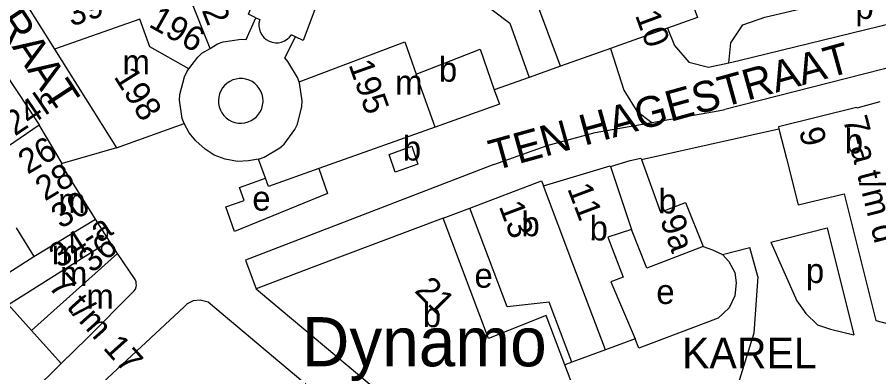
# Model space of a CAD drawing. Extents: x 160673 to 161924, y 382258 to 384145.
# Drawn here: x 161438.3 to 161578.5, y 383169.3 to 383227.2 of the extents above; entities that cross this region are included whole.
import ezdxf

# ---------------------------------------------------------------- set-up
doc = ezdxf.new("R2010")
doc.units = 0
for name, color, linetype in [('BLT_Basislijn', 7, 'Continuous'), ('BLT_Bebouwing', 7, 'Continuous'), ('BLT_Bebouwing_beschrifting', 7, 'Continuous'), ('BLT_Centroide', 7, 'Continuous'), ('BLT_Huisnummer', 7, 'Continuous'), ('BLT_Huisnummer_reeks', 7, 'Continuous'), ('BLT_Onderverdeling_panden', 7, 'Continuous'), ('BLT_Straatnaam', 7, 'Continuous'), ('BLT_Vlakafsluiter', 7, 'Continuous')]:
    doc.layers.add(name, color=color, linetype=linetype)

msp = doc.modelspace()

# ---------------------------------------------------------------- linework, layer by layer
at = {"layer": 'BLT_Basislijn'}
for p, q in [((161608.47, 383226.14), (161553.47, 383212.15)), ((161541.58, 383210.02), (161552.39, 383211.91)), ((161552.39, 383211.91), (161553.47, 383212.15)), ((161539.92, 383203.99), (161562.24, 383209)), ((161507.62, 383194.44), (161512, 383196.09)), ((161560.96, 383190.54), (161570.14, 383192.89)), ((161553.08, 383188.52), (161557.52, 383189.66)), ((161528.58, 383171), (161527.45, 383170.59))]:
    msp.add_line(p, q, dxfattribs=at)
for points in [[(161554.12, 383219.74), (161554.47, 383223.02), (161556.42, 383225.91), (161559.99, 383227.18), (161594.98, 383235.4), (161599.22, 383233.8)], [(161554.12, 383219.74), (161555.77, 383220.1), (161601.53, 383231.34)], [(161544.14, 383225.4), (161545.29, 383222.57), (161547.63, 383219.86), (161550.8, 383219.01), (161554.12, 383219.74)], [(161534.87, 383222.09), (161537.05, 383215.31), (161539.13, 383211.89), (161541.58, 383210.02)], [(161478.33, 383213.55), (161478.29, 383214.09), (161478.17, 383214.61), (161477.98, 383215.11), (161477.71, 383215.58), (161477.38, 383216), (161476.98, 383216.37), (161476.54, 383216.68), (161476.06, 383216.92), (161475.54, 383217.08), (161475.01, 383217.17), (161474.47, 383217.17), (161473.94, 383217.1), (161473.42, 383216.95), (161472.93, 383216.72), (161472.48, 383216.43), (161472.08, 383216.07), (161471.74, 383215.65), (161471.46, 383215.19), (161471.25, 383214.69), (161471.12, 383214.17), (161471.07, 383213.64), (161471.1, 383213.1), (161471.2, 383212.57), (161471.39, 383212.06), (161471.64, 383211.59), (161471.97, 383211.16), (161472.35, 383210.78), (161472.79, 383210.46), (161473.26, 383210.21), (161473.77, 383210.04), (161474.3, 383209.94), (161474.84, 383209.92), (161475.37, 383209.98), (161475.89, 383210.12), (161476.39, 383210.34), (161476.85, 383210.62), (161477.26, 383210.97), (161477.61, 383211.38), (161477.9, 383211.83), (161478.12, 383212.32), (161478.26, 383212.84), (161478.33, 383213.38), (161478.33, 383213.55)], [(161477.62, 383204.04), (161475.99, 383203.79), (161474.17, 383203.7), (161472.15, 383204.07), (161470.39, 383204.71), (161468.89, 383205.67), (161467.38, 383207.04), (161466.33, 383208.33), (161465.48, 383209.86)], [(161515.87, 383203.21), (161524.58, 383206.29), (161532.36, 383208.39), (161541.58, 383210.02)], [(161515.87, 383203.21), (161475.47, 383187.61), (161477.23, 383182.96)], [(161487.41, 383202.53), (161488.84, 383198.48)], [(161473.69, 383192.29), (161472.29, 383196.3), (161475.25, 383197.34), (161474.51, 383199.44), (161478.75, 383200.96)], [(161488.84, 383198.48), (161473.69, 383192.29)], [(161549.92, 383189.82), (161551.47, 383189.28), (161553.08, 383188.52)], [(161558.84, 383184.96), (161557.52, 383189.66)], [(161560.96, 383190.54), (161565.18, 383181.02), (161566.66, 383178.94), (161568.56, 383177.12), (161570.68, 383176.37), (161574.47, 383175.48)], [(161553.08, 383188.52), (161554.1, 383187.38), (161555.08, 383185.59), (161555.32, 383183.91), (161555.12, 383181.79), (161554.17, 383179.89), (161552.37, 383178.17), (161539.45, 383173.28), (161538.87, 383174.83)], [(161558.84, 383184.96), (161558.18, 383175.74), (161555.16, 383165.91), (161549.27, 383153.85), (161548.57, 383152.74), (161546.98, 383149.44), (161541.17, 383143.92)], [(161485.03, 383165.97), (161485.83, 383166.97), (161470.47, 383179.86), (161469.39, 383180.76), (161468.12, 383181.13), (161466.99, 383181.02), (161466.01, 383180.53), (161465.51, 383180.03), (161432.72, 383149.6), (161432.07, 383148.78), (161431.81, 383147.93), (161431.86, 383146.84), (161432.5, 383145.53), (161446.92, 383128.91), (161448.52, 383130.38)]]:
    msp.add_lwpolyline(points, dxfattribs=at)
at = {"layer": 'BLT_Bebouwing'}
for p, q in [((161478.75, 383200.96), (161477.62, 383204.04)), ((161479.24, 383199.61), (161478.75, 383200.96)), ((161453.36, 383190.71), (161451.1, 383194.27)), ((161454.64, 383188.7), (161453.36, 383190.71)), ((161457.54, 383184.45), (161454.64, 383188.7)), ((161486.19, 383186.35), (161477.23, 383182.96)), ((161477.62, 383182.63), (161516.83, 383149.75)), ((161534.05, 383173.01), (161528.58, 383171)), ((161529.67, 383164.74), (161527.45, 383170.59))]:
    msp.add_line(p, q, dxfattribs=at)
for points in [[(161441.57, 383231.12), (161439.44, 383229.84), (161444.39, 383221.97)], [(161551.93, 383231.15), (161548.05, 383229.78), (161549.02, 383227.14), (161544.14, 383225.4)], [(161469.72, 383222.09), (161470.94, 383222.81), (161471.82, 383223.14), (161474.76, 383223.57), (161475.58, 383223.52), (161477.14, 383227.08)], [(161477.14, 383227.08), (161477.79, 383226.77)], [(161477.79, 383226.77), (161477.67, 383226.22), (161477.65, 383225.73), (161477.73, 383225.2), (161477.85, 383224.81), (161478.14, 383224.27), (161478.46, 383223.87), (161478.84, 383223.54), (161479.32, 383223.26), (161479.83, 383223.08), (161480.35, 383222.99), (161480.87, 383223.01), (161481.36, 383223.11), (161481.85, 383223.3), (161482.28, 383223.57), (161482.66, 383223.91), (161482.96, 383224.3)], [(161544.14, 383225.4), (161534.87, 383222.09)], [(161484.23, 383216.62), (161483.95, 383217.36), (161482.39, 383219.93), (161481.86, 383220.55), (161483.64, 383223.98)], [(161483.64, 383223.98), (161482.96, 383224.3)], [(161444.39, 383221.97), (161454.47, 383205.92)], [(161466.26, 383218.74), (161467.71, 383220.67), (161468.39, 383221.31), (161469.72, 383222.09)], [(161534.87, 383222.09), (161526.73, 383219.19)], [(161434.47, 383220.8), (161441.92, 383209.63)], [(161526.73, 383219.19), (161521.62, 383217.37)], [(161454.47, 383205.92), (161465.48, 383209.86), (161465.18, 383210.7), (161464.76, 383213.64), (161464.8, 383214.58), (161465.54, 383217.46), (161465.92, 383218.3), (161466.26, 383218.74)], [(161521.62, 383217.37), (161515.96, 383215.34)], [(161477.62, 383204.04), (161478.5, 383204.37), (161481.05, 383205.89), (161481.75, 383206.52), (161483.52, 383208.9), (161483.92, 383209.74), (161484.67, 383212.64), (161484.7, 383213.58), (161484.27, 383216.51), (161484.23, 383216.62)], [(161515.96, 383215.34), (161516.79, 383213.01)], [(161578.69, 383213.41), (161574.95, 383212.36), (161574.91, 383212.48), (161562.22, 383209.32), (161562.24, 383209)], [(161516.79, 383213.01), (161506.32, 383209.27)], [(161445.63, 383203.34), (161441.92, 383209.63)], [(161506.32, 383209.27), (161487.41, 383202.53)], [(161562.24, 383209), (161563.49, 383204.16), (161565.39, 383196.62), (161572.89, 383198.41), (161574.02, 383193.88)], [(161534.89, 383202.87), (161538.04, 383203.83), (161539.81, 383204.22), (161539.92, 383203.99)], [(161539.92, 383203.99), (161542.99, 383195.43), (161547.06, 383196.99), (161549.92, 383189.82)], [(161451.1, 383194.27), (161445.47, 383203.23), (161445.63, 383203.34)], [(161487.41, 383202.53), (161479.24, 383199.61)], [(161523.98, 383199.7), (161534.82, 383202.97), (161534.89, 383202.87)], [(161512, 383196.09), (161523.66, 383200.51), (161523.98, 383199.7)], [(161528.58, 383171), (161524.88, 383180.78), (161518.08, 383180.01), (161512, 383196.09)], [(161507.62, 383194.44), (161486.19, 383186.35)], [(161527.45, 383170.59), (161524.42, 383178.6), (161515.02, 383174.89), (161507.62, 383194.44)], [(161574.02, 383193.88), (161578.02, 383177.79), (161580.09, 383177.28)], [(161538.28, 383192.59), (161534.43, 383191.37), (161536.93, 383184.87), (161534.93, 383184.1), (161538.87, 383174.83)], [(161549.92, 383189.82), (161540.78, 383186.34), (161538.28, 383192.59)], [(161457.58, 383182.92), (161457.69, 383183.27), (161457.73, 383183.5), (161457.71, 383183.8), (161457.69, 383184.1), (161457.54, 383184.45)], [(161445.49, 383170.79), (161449.76, 383174.99), (161457.33, 383182.58), (161457.58, 383182.92)], [(161477.23, 383182.96), (161477.62, 383182.63)], [(161538.87, 383174.83), (161534.05, 383173.01)], [(161428.87, 383155.76), (161430.75, 383156.28), (161445.49, 383170.79)]]:
    msp.add_lwpolyline(points, dxfattribs=at)
msp.add_lwpolyline([(161498.86, 383204.84), (161502.56, 383206.17), (161503.53, 383203.27), (161499.83, 383201.94)], close=True, dxfattribs=at)
at = {"layer": 'BLT_Huisnummer_reeks'}
msp.add_lwpolyline([(161570.14, 383192.89), (161574.47, 383175.48)], dxfattribs=at)
at = {"layer": 'BLT_Onderverdeling_panden'}
for p, q in [((161469.72, 383222.09), (161463.33, 383238.28)), ((161526.73, 383219.19), (161520.94, 383234.83)), ((161506.32, 383209.27), (161503.24, 383217.9)), ((161534.89, 383202.87), (161538.28, 383192.59)), ((161528.74, 383187.04), (161523.98, 383199.7)), ((161441.02, 383188.2), (161451.1, 383194.27)), ((161438.16, 383192.89), (161441.02, 383188.2)), ((161453.36, 383190.71), (161436.92, 383180.36)), ((161440.65, 383176.19), (161454.64, 383188.7)), ((161436.92, 383180.36), (161440.65, 383176.19)), ((161440.65, 383176.19), (161445.49, 383170.79))]:
    msp.add_line(p, q, dxfattribs=at)
for points in [[(161502.61, 383243.22), (161504.96, 383236.44), (161518.48, 383226.17), (161521.62, 383217.37)], [(161477.14, 383227.08), (161475.96, 383227.64), (161481.05, 383240.47)], [(161490.11, 383237.41), (161484.84, 383223.4), (161483.64, 383223.98)], [(161466.26, 383218.74), (161459.92, 383222.32), (161458.31, 383226.87), (161444.39, 383221.97)], [(161484.23, 383216.62), (161501.38, 383223.14), (161503.24, 383217.9)], [(161503.24, 383217.9), (161513.64, 383221.94), (161515.96, 383215.34)], [(161431.39, 383202.5), (161437.76, 383206.85), (161441.92, 383209.63)], [(161432.52, 383182.79), (161441.02, 383188.2)], [(161534.05, 383173.01), (161528.74, 383187.04)]]:
    msp.add_lwpolyline(points, dxfattribs=at)
at = {"layer": 'BLT_Vlakafsluiter'}
msp.add_line((161454.47, 383205.92), (161445.63, 383203.34), dxfattribs=at)

# ---------------------------------------------------------------- texts
at = {"layer": 'BLT_Bebouwing_beschrifting'}
msp.add_text('Dynamo', height=8, rotation=359.9999, dxfattribs=at).set_placement((161484.65, 383170.35))
at = {"layer": 'BLT_Centroide'}
for s, p in [('p', (161574.71, 383226.89)), ('m', (161455.47, 383217.88)), ('b', (161506.95, 383216.67)), ('m', (161499.83, 383214.56)), ('b', (161572.98, 383205.02)), ('b', (161501.08, 383203.84)), ('b', (161542.67, 383195.22)), ('m', (161445.01, 383195.31)), ('e', (161476.59, 383195.68)), ('b', (161520.38, 383191.52)), ('b', (161531.47, 383190.83)), ('m', (161443.96, 383186.92)), ('m', (161445.29, 383183.44)), ('p', (161566.66, 383183.91)), ('e', (161512.73, 383183.14)), ('m', (161449.59, 383179.75)), ('e', (161542.32, 383180.49)), ('b', (161504.33, 383176.72))]:
    msp.add_text(s, height=4, dxfattribs=at).set_placement(p)
at = {"layer": 'BLT_Huisnummer'}
for s, rotation, p in [('11', 290.6803, (161527.8, 383199.3)), ('13', 290.7362, (161516.65, 383196.4)), ('9a', 289.7553, (161542.89, 383194.19)), ('36', 41.8059, (161450.54, 383185.38)), ('21', 314.6803, (161502.84, 383182.55))]:
    msp.add_text(s, height=4, rotation=rotation, dxfattribs=at).set_placement(p)
at = {"layer": 'BLT_Huisnummer_reeks'}
for s, rotation, p in [('4 t/m 10', 290.309, (161534.18, 383240.03)), ('192', 291.5492, (161466.13, 383233.84)), ('39', 19.3888, (161447.17, 383225.59)), ('196', 330.5687, (161459.56, 383225.72)), ('198', 302.0562, (161453.96, 383217.49)), ('195', 289.5986, (161492.21, 383219.46)), ('24a t/m 24h', 34.3732, (161422.01, 383196.81)), ('7-a t/m d', 284.4309, (161572.66, 383210.57)), ('9', 284.4309, (161565.5, 383208.73)), ('26', 30.5765, (161440.03, 383201.51)), ('28', 31.205, (161442.85, 383197.14)), ('30', 31.205, (161445.43, 383192.63)), ('34-a', 32.6309, (161445.18, 383186.2)), ('7 t/m 17', 311.8132, (161443.25, 383183.25))]:
    msp.add_text(s, height=4, rotation=rotation, dxfattribs=at).set_placement(p)
at = {"layer": 'BLT_Straatnaam'}
for s, rotation, p in [('JAN VAN LIESHOUTSTRAAT', 303.3195, (161395.14, 383286.62)), ('TEN HAGESTRAAT', 15.4954, (161515.94, 383202.16))]:
    msp.add_text(s, height=5, rotation=rotation, dxfattribs=at).set_placement(p)
msp.add_text('KAREL', height=5, dxfattribs=at).set_placement((161546.5, 383170.02))

doc.saveas('drawing.dxf')
